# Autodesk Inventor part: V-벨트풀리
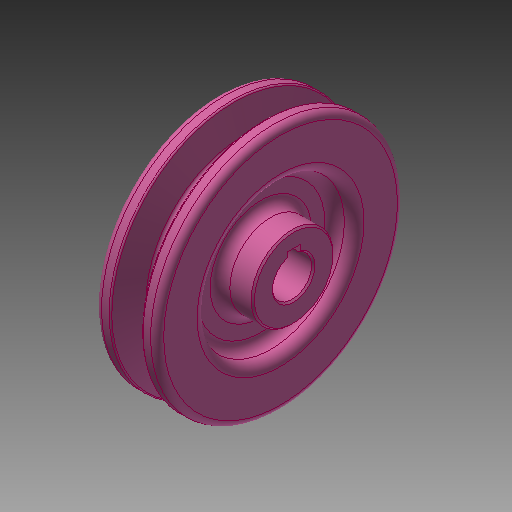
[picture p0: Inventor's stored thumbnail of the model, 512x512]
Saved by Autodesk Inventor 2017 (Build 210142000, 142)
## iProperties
Created: 2015-11
Part Number: V-벨트풀리
Material: 강철, 탄소
Document SubType Name: Modeling
Designer: mduedu
Density: 1 g/cm^3
Appearance: 분홍색
Author: mduedu
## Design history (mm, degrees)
sketch "스케치1"
  geometry: L1 (-9.5, 0)-(9.5, 0); L2 (0, 0)-(0, 37.7); L3 (-4.825, 37.7)-(-9.5, 37.7); L4 (-9.5, 37.7)-(-9.5, 0); L5 (0, 28.7)-(-2.074, 28.7); L6 (-2.074, 28.7)-(-4.825, 37.7); L7 (4.825, 37.7)-(9.5, 37.7); L8 (9.5, 37.7)-(9.5, 0); L9 (0, 28.7)-(2.074, 28.7); L10 (2.074, 28.7)-(4.825, 37.7); L11 (-9.5, 35)-(9.5, 35); 3 further points
  constraints: 22 end point, 7 point on line, 4 perpendicular, 3 symmetric about line, 1 coincident, 1 horizontal, 1 horizontal alignment, 1 midpoint, 1 vertical
  dimensions: "d0" = 19 distance of L1.start L1.end; "d2" = 75.4 diameter of L2.end L1 (derived); "d3" = 34 deg angle of L10 L6; "d4" = 6.3 distance between parallel lines of L11 L9; "d5" = 2.7 distance between parallel lines of L7 L11; "d6" = 8 distance of point (4, 35) point (-4, 35); "d7" = 70 diameter of L11 L1
revolve "회전1" sketch "스케치1" stored, may be unused: angle "d8" = 90 deg
sketch "스케치2"
  geometry: C1 r 22.5 at (0, 0); C2 r 12.5 at (0, 0); C3 r 37.7 at (0, 0) reference; 1 further point
  constraints: 2 centre point, 2 coincident
  dimensions: "d35" = 15.2 radial gap between concentric circles of C3 C1 (computed from d5); "d36" = 10 radial gap between concentric circles of C1 C2
extrude "돌출1" cut sketch "스케치2" distance "d11" = 6; taper "d12" = 0 deg
fillet "모깎기1" dims "d13" = 3
feature "면 이동1"
fillet "모깎기2" dims "d14" = 3
fillet "모깎기3" dims "d15" = 1, "d16" = 0.5, "d17" = 2
hole "구멍1" diameter "d20" = 12; stored, may be unused: countersink angle "d24" = 90 deg, drill point angle "d26" = 118 deg; dims "d21" = 6, "d22" = 4, "d23" = 2, "d25" = 8, "d37" = 10, "d38" = 10
sketch "스케치3"
  geometry: L1 (-2, 0)-(2, 0); L2 (2, 0)-(2, 7.8); L3 (2, 7.8)-(-2, 7.8); L4 (-2, 7.8)-(-2, 0); C1 r 12.5 at (0, 0) reference; 2 further points
  constraints: 8 end point, 2 coincident, 2 parallel, 1 horizontal, 1 midpoint, 1 perpendicular
  dimensions: "d27" = 4 distance of L2.end L3.end; "d29" = 7.8 distance of L3.end L1.start
extrude "돌출2" cut sketch "스케치3" stored distance "d30" = 6; taper "d31" = 0 deg
chamfer "모따기1" distance "d32" = 0.5; stored, may be unused: second distance "d33" = 2, angle "d34" = 45 deg
node "솔리드1"
mirror "대칭1"
